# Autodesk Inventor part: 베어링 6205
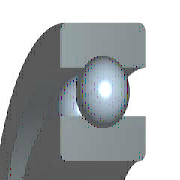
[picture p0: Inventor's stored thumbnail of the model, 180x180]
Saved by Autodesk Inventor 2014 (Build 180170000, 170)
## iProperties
Created: 2015-10
Part Number: 베어링 6205
Material: 강, 연강
Description: 깊은 그루브 볼 베어링
Document SubType Name: Modeling
Standard: KS B 2023
Designer: mdu
Standards Organization: KS
Language: ko-KR
Size Designation: 6205 - 25 x 52 x 15
Categories: <MemberInstance><Categories><Category DisplayName="샤프트 부품" InternalName="7f7aeb1f-a693-4053-b835-cee3144e0d98" Mnemonic="SHFT"><Category DisplayName="베어링" Inter
Density: 7.86 g/cm^3
Appearance: Yellow
Mass: 116.729 g
Surface Area: 107.326 cm^2
Volume: 14.851 cm^3
IsCustomPart: 1
Author: mdu
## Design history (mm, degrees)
sketch "스케치" dims "d0" = 7.02 (= -0.26 x WD + 0.26 x BD)
  geometry: L1 (3.99, 19.25)-(11.01, 19.25); L2 (7.5, 19.25)-(7.5, 15.74); L3 (7.5, 19.25)-(7.5, 22.76); L4 (4.892, 16.901)-(0, 16.901); L5 (0, 12.5)-(15, 12.5); L6 (4.892, 21.599)-(0, 21.599); L7 (0, 26)-(15, 26); L8 (15, 12.5)-(15, 16.901); L9 (10.108, 16.901)-(15, 16.901); L10 (10.108, 21.599)-(15, 21.599); L11 (15, 26)-(15, 21.599); L12 (-1.4, 0)-(8.4, 0) reference; L13 (0, -0.3)-(0, 5.3) reference
  constraints: 22 end point, 4 point on line, 2 collinear, 2 perpendicular, 2 symmetric about line, 1 midpoint, 1 parallel, 14 other
  dimensions: "d9" = 25 diameter of L5 L12 (= WD); "d11" = 52 diameter of L7 L12 (= BD); "d12" = 15 distance between parallel lines of L8 L13 (= KB); "d13" = 33.802 diameter of L9 L12 (= 0.326 x BD + 0.674 x WD)
revolve "본체" stored, may be unused: angle "d6" = 90 deg
revolve "볼" stored, may be unused: angle "d7" = 90 deg
pattern_circular "IDS_ARRAYBALL[SIMPL:T]" dims angle "d3" = 360 deg
body "Solid1"
fillet "모깎기1" dims "d1" = 1 (= KRS)
other parameters: "WD" = 25 [user parameter; used in 5 equation terms], "BD" = 52 [user parameter; used in 5 equation terms], "KB" = 15 [user parameter; used in 1 equation term], "KRS" = 1 [user parameter; used in 1 equation term], "d4" = 0, "d5" = 0, "d8" = 0, "d14" = 0, "d15" = 0, "BBA" = 0 [user parameter], "BC0" = 7800000 [user parameter], "BC" = 1.4e+07 [user parameter], "BR" = 26 (= 0.5 x BD) [user parameter], "WR" = 12.5 (= 0.5 x WD) [user parameter]
